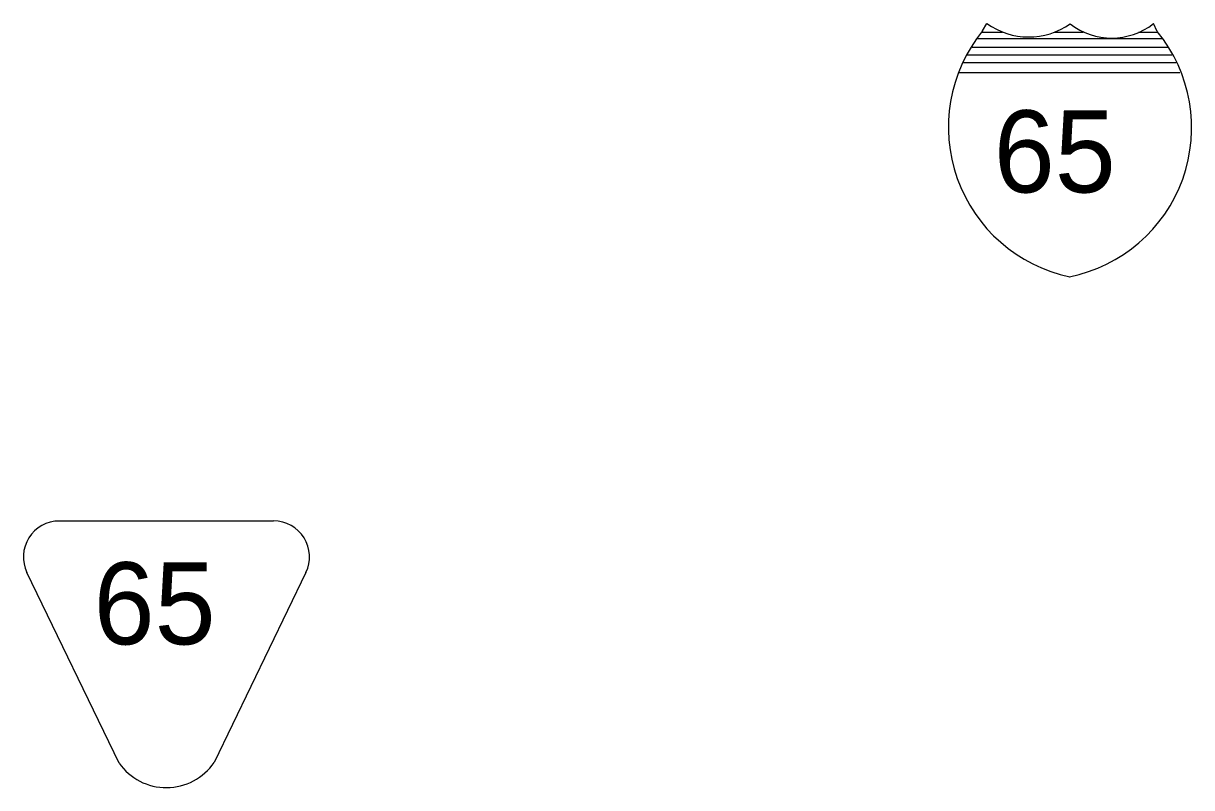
# Model space of a CAD drawing. Extents: x 1612280 to 1883141, y 560852 to 780851.
# Drawn here: x 1735387 to 1741404, y 683674 to 687607 of the extents above; entities that cross this region are included whole.
import ezdxf

# ---------------------------------------------------------------- set-up
doc = ezdxf.new("R2010")
doc.units = 0
doc.layers.add('DESIGN - ROW - Easement Linework and Patterning', color=7, linetype='Continuous')
doc.layers.add('SURVEY - DRAINAGE - Bridge Hydraulic Data with Text', color=7, linetype='Continuous')

msp = doc.modelspace()

# ---------------------------------------------------------------- linework, layer by layer
at = {"layer": 'DESIGN - ROW - Easement Linework and Patterning'}
for p, q in [((1736675.8, 685046.1), (1735571.5, 685046.1)), ((1736675.8, 685046.1), (1735571.5, 685046.1)), ((1735879.6, 683800.3), (1735405.1, 684780.8)), ((1735879.6, 683800.3), (1735405.1, 684780.8)), ((1736842.2, 684780.9), (1736369.1, 683803.3)), ((1736842.2, 684780.9), (1736369.1, 683803.3))]:
    msp.add_line(p, q, dxfattribs=at)
for centre, radius, start, end in [((1735571.5, 684861.3), 184.8, 90.00121, 205.8236), ((1735571.5, 684861.3), 184.8, 90.00121, 205.8236), ((1736675.8, 684861.4), 184.8, 334.17992, 90.00121), ((1736675.8, 684861.4), 184.8, 334.17992, 90.00121), ((1736123.3, 683971.9), 298.1, 215.13706, 325.54513), ((1736123.3, 683971.9), 298.1, 215.13706, 325.54513)]:
    msp.add_arc(centre, radius, start, end, dxfattribs=at)
at = {"layer": 'SURVEY - DRAINAGE - Bridge Hydraulic Data with Text'}
for p, q in [((1740297.1, 687529.4), (1741254.9, 687529.4)), ((1740297.1, 687529.4), (1741254.9, 687529.4)), ((1740322.7, 687562.3), (1740429.3, 687562.3)), ((1740322.7, 687562.3), (1740429.3, 687562.3)), ((1740698.6, 687562.3), (1740845.8, 687562.3)), ((1740698.6, 687562.3), (1740845.8, 687562.3)), ((1741131.3, 687562.3), (1741231.1, 687562.3)), ((1741131.3, 687562.3), (1741231.1, 687562.3)), ((1740273.7, 687485.2), (1741279.7, 687485.2)), ((1740273.7, 687485.2), (1741279.7, 687485.2)), ((1740226.9, 687405.9), (1741323.9, 687405.9)), ((1740226.9, 687405.9), (1741323.9, 687405.9)), ((1740247.7, 687446.2), (1741303.1, 687446.2)), ((1740247.7, 687446.2), (1741303.1, 687446.2)), ((1740206.1, 687355.1), (1741343.4, 687355.2)), ((1740206.1, 687355.1), (1741343.4, 687355.2))]:
    msp.add_line(p, q, dxfattribs=at)
for points in [[(1740326.8, 687568.6), (1740349.4, 687607.5)], [(1740326.8, 687568.6), (1740349.4, 687607.5)], [(1741227.5, 687565.4), (1741207.7, 687606.2)], [(1741227.5, 687565.4), (1741207.7, 687606.2)]]:
    msp.add_lwpolyline(points, dxfattribs=at)
for centre, radius, start, end in [((1740565.8, 687907.1), 369.6, 234.16469, 305.14405), ((1740565.8, 687907.1), 369.6, 234.16469, 305.14405), ((1740992.3, 687882), 350, 232.36249, 307.98764), ((1740992.3, 687882), 350, 232.36249, 307.98764), ((1740938, 687073.4), 786.7, 140.99011, 258.17805), ((1740938, 687073.4), 786.7, 140.99011, 258.17805), ((1740622.5, 687070.3), 781.8, 281.22259, 39.2925), ((1740622.5, 687070.3), 781.8, 281.22259, 39.2925)]:
    msp.add_arc(centre, radius, start, end, dxfattribs=at)

# ---------------------------------------------------------------- texts
at = {"layer": 'DESIGN - ROW - Easement Linework and Patterning'}
msp.add_text('65', height=422.41, rotation=0.00121, dxfattribs=at).set_placement((1735748.5, 684411.2))
msp.add_text('65', height=422.41, rotation=0.00121, dxfattribs=at).set_placement((1735748.5, 684411.2))
at = {"layer": 'SURVEY - DRAINAGE - Bridge Hydraulic Data with Text'}
msp.add_text('65', height=422.4, rotation=0.00131, dxfattribs=at).set_placement((1740385.1, 686737.4))
msp.add_text('65', height=422.4, rotation=0.00131, dxfattribs=at).set_placement((1740385.1, 686737.4))

doc.saveas('drawing.dxf')
